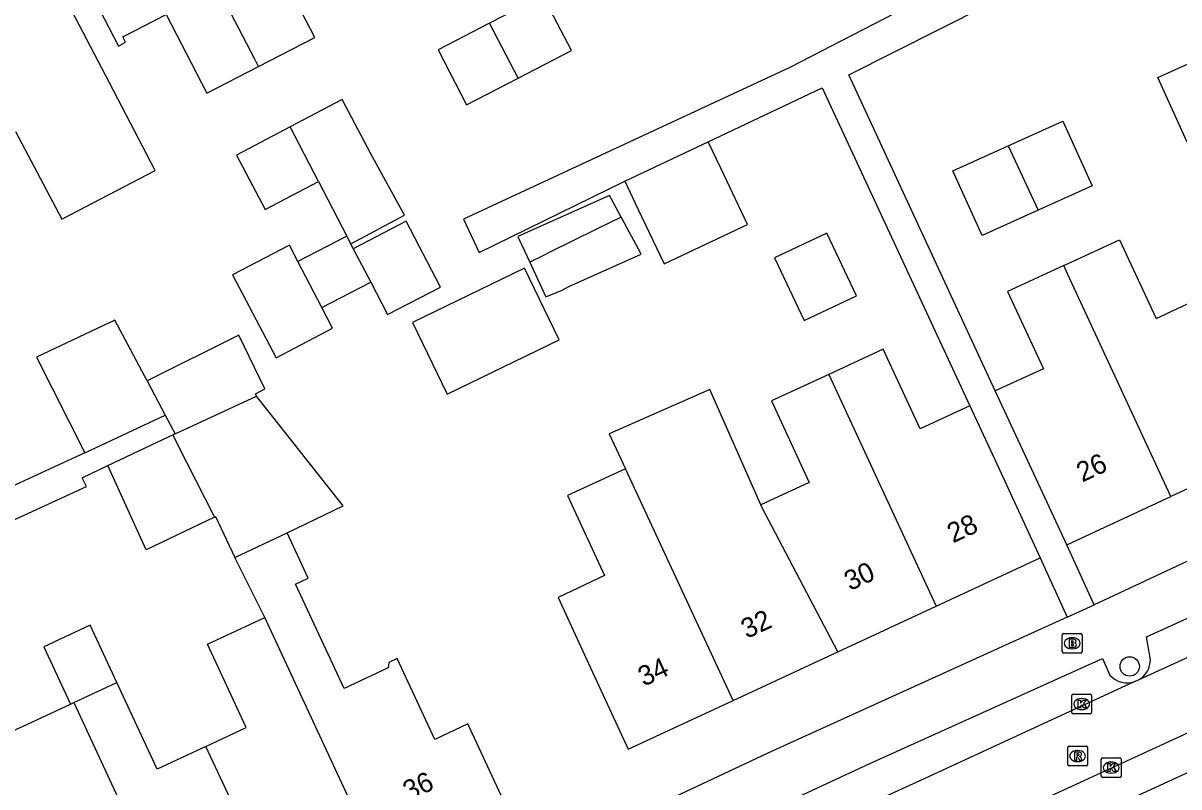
# Model space of a CAD drawing. Extents: x 159265 to 160143, y 383413 to 384319.
# Drawn here: x 159391.1 to 159449.6, y 384205.5 to 384244.2 of the extents above; entities that cross this region are included whole.
import ezdxf

# ---------------------------------------------------------------- set-up
doc = ezdxf.new("R2010")
doc.units = 0
for name, color, linetype in [('IMGEO_Boom', 7, 'Continuous'), ('IMGEO_Brandkraan', 7, 'Continuous'), ('IMGEO_Kolk', 7, 'Continuous'), ('IMGEO_Pand', 7, 'Continuous'), ('IMGEO_Pand_nummerreeks', 7, 'Continuous'), ('IMGEO_Rijbaan_lokaal_open', 7, 'Continuous'), ('IMGEO_Rioolput', 7, 'Continuous'), ('IMGEO_Voetpad_open', 7, 'Continuous')]:
    doc.layers.add(name, color=color, linetype=linetype)

msp = doc.modelspace()

# ---------------------------------------------------------------- linework, layer by layer
at = {"layer": 'IMGEO_Boom'}
msp.add_circle((159447.097, 384211.641), 0.489, dxfattribs=at)
at = {"layer": 'IMGEO_Brandkraan'}
for p, q in [((159443.687, 384212.388), (159443.687, 384213.24)), ((159443.762, 384213.314), (159444.614, 384213.314)), ((159444.688, 384213.24), (159444.688, 384212.388)), ((159444.175, 384213.094), (159444.2, 384213.094)), ((159444.614, 384212.314), (159443.762, 384212.314)), ((159444.198, 384212.534), (159444.173, 384212.534))]:
    msp.add_line(p, q, dxfattribs=at)
for points in [[(159443.687, 384212.388), (159443.687, 384213.24)], [(159443.762, 384213.314), (159444.614, 384213.314)], [(159444.688, 384213.24), (159444.688, 384212.388)], [(159444.035, 384213.014), (159444.035, 384212.614), (159444.248, 384212.614)], [(159444.266, 384213.014), (159444.035, 384213.014)], [(159444.214, 384212.933), (159444.16, 384212.933), (159444.16, 384212.857)], [(159444.16, 384212.857), (159444.213, 384212.857)], [(159444.222, 384212.781), (159444.16, 384212.781), (159444.16, 384212.7)], [(159444.16, 384212.7), (159444.222, 384212.7)], [(159444.614, 384212.314), (159443.762, 384212.314)]]:
    msp.add_lwpolyline(points, dxfattribs=at)
for centre, radius, start, end in [((159443.764, 384213.238), 0.0765, 91.55205, 178.44795), ((159443.764, 384213.238), 0.0765, 91.55205, 178.44795), ((159444.612, 384213.238), 0.0765, 1.55205, 88.44795), ((159444.612, 384213.238), 0.0765, 1.55205, 88.44795), ((159444.215, 384212.895), 0.0379, 267.82845, 90.93552), ((159444.223, 384212.74), 0.0404, 269.87594, 90.50774), ((159444.27, 384212.869), 0.145, 59.4692, 91.53667), ((159444.295, 384212.916), 0.0922, 285.51372, 58.15012), ((159444.3, 384212.724), 0.105, 301.31148, 78.98903), ((159443.764, 384212.39), 0.0765, 181.55205, 268.44795), ((159443.764, 384212.39), 0.0765, 181.55205, 268.44795), ((159444.254, 384212.865), 0.251, 268.66757, 293.53466), ((159444.612, 384212.39), 0.0765, 271.55205, 358.44795), ((159444.612, 384212.39), 0.0765, 271.55205, 358.44795)]:
    msp.add_arc(centre, radius, start, end, dxfattribs=at)
for centre, major_axis, ratio, start_param, end_param in [((159444.174, 384212.814), (-0.387, 0.002), 0.722429, 4.712389, 7.853982), ((159444.199, 384212.814), (-0.39, 0.002), 0.717154, 1.570796, 4.712389)]:
    msp.add_ellipse(centre, major_axis=major_axis, ratio=ratio, start_param=start_param, end_param=end_param, dxfattribs=at)
at = {"layer": 'IMGEO_Kolk'}
for p, q in [((159444.17, 384209.316), (159444.17, 384210.168)), ((159444.245, 384210.242), (159445.097, 384210.242)), ((159444.658, 384210.022), (159444.683, 384210.022)), ((159445.171, 384210.168), (159445.171, 384209.316)), ((159445.097, 384209.242), (159444.245, 384209.242)), ((159444.681, 384209.462), (159444.656, 384209.462)), ((159445.663, 384206.099), (159445.663, 384206.951)), ((159445.738, 384207.025), (159446.59, 384207.025)), ((159446.151, 384206.805), (159446.176, 384206.805)), ((159446.664, 384206.951), (159446.664, 384206.099)), ((159446.174, 384206.245), (159446.149, 384206.245)), ((159446.59, 384206.025), (159445.738, 384206.025))]:
    msp.add_line(p, q, dxfattribs=at)
for points in [[(159444.17, 384209.316), (159444.17, 384210.168)], [(159444.245, 384210.242), (159445.097, 384210.242)], [(159444.491, 384209.942), (159444.614, 384209.942), (159444.614, 384209.791), (159444.744, 384209.942), (159444.908, 384209.942), (159444.762, 384209.791), (159444.915, 384209.542), (159444.763, 384209.542), (159444.678, 384209.706), (159444.614, 384209.639), (159444.614, 384209.542), (159444.491, 384209.542), (159444.491, 384209.942)], [(159445.171, 384210.168), (159445.171, 384209.316)], [(159445.097, 384209.242), (159444.245, 384209.242)], [(159445.663, 384206.099), (159445.663, 384206.951)], [(159445.738, 384207.025), (159446.59, 384207.025)], [(159446.664, 384206.951), (159446.664, 384206.099)], [(159445.984, 384206.725), (159446.107, 384206.725), (159446.107, 384206.574), (159446.237, 384206.725), (159446.401, 384206.725), (159446.255, 384206.574), (159446.408, 384206.325), (159446.256, 384206.325), (159446.171, 384206.489), (159446.107, 384206.422), (159446.107, 384206.325), (159445.984, 384206.325), (159445.984, 384206.725)], [(159446.59, 384206.025), (159445.738, 384206.025)]]:
    msp.add_lwpolyline(points, dxfattribs=at)
for centre, start, end in [((159444.247, 384210.166), 91.55205, 178.44795), ((159444.247, 384210.166), 91.55205, 178.44795), ((159445.095, 384210.166), 1.55205, 88.44795), ((159445.095, 384210.166), 1.55205, 88.44795), ((159444.247, 384209.318), 181.55205, 268.44795), ((159444.247, 384209.318), 181.55205, 268.44795), ((159445.095, 384209.318), 271.55205, 358.44795), ((159445.095, 384209.318), 271.55205, 358.44795), ((159445.74, 384206.949), 91.55205, 178.44795), ((159445.74, 384206.949), 91.55205, 178.44795), ((159446.588, 384206.949), 1.55205, 88.44795), ((159446.588, 384206.949), 1.55205, 88.44795), ((159445.74, 384206.101), 181.55205, 268.44795), ((159445.74, 384206.101), 181.55205, 268.44795), ((159446.588, 384206.101), 271.55205, 358.44795), ((159446.588, 384206.101), 271.55205, 358.44795)]:
    msp.add_arc(centre, 0.0765, start, end, dxfattribs=at)
for centre, major_axis, ratio, start_param, end_param in [((159444.657, 384209.742), (-0.387, 0.002), 0.722429, 4.712389, 7.853982), ((159444.682, 384209.742), (-0.39, 0.002), 0.717154, 1.570796, 4.712389), ((159446.15, 384206.525), (-0.387, 0.002), 0.722429, 4.712389, 7.853982), ((159446.175, 384206.525), (-0.39, 0.002), 0.717154, 1.570796, 4.712389)]:
    msp.add_ellipse(centre, major_axis=major_axis, ratio=ratio, start_param=start_param, end_param=end_param, dxfattribs=at)
at = {"layer": 'IMGEO_Pand'}
for points in [[(159403.053, 384241.99), (159402.858, 384242.366), (159398.89, 384250), (159397.074, 384253.494)], [(159391.947, 384250.825), (159392.372, 384250), (159395.969, 384243.009), (159396.322, 384243.219), (159396.182, 384243.491), (159398.382, 384244.625), (159400.435, 384240.641), (159403.053, 384241.99)], [(159390.768, 384238.692), (159393.102, 384234.267), (159397.827, 384236.735), (159395.511, 384241.169), (159393.22, 384245.555), (159390.963, 384250), (159390.833, 384250.255)], [(159403.053, 384241.99), (159405.892, 384243.452), (159403.876, 384247.366), (159406.076, 384248.5)], [(159416.175, 384241.394), (159418.869, 384242.793), (159417.423, 384245.577), (159414.729, 384244.178)], [(159414.729, 384244.178), (159412.126, 384242.826), (159413.572, 384240.042), (159416.175, 384241.394)], [(159416.175, 384241.394), (159414.729, 384244.178)], [(159452.828, 384239.442), (159449.999, 384238.16), (159448.517, 384241.429), (159451.317, 384242.698)], [(159407.714, 384233.022), (159410.425, 384234.463), (159408.73, 384237.571), (159407.282, 384240.32), (159404.644, 384238.93)], [(159440.96, 384237.972), (159443.712, 384239.219), (159445.194, 384235.95), (159442.471, 384234.716)], [(159404.644, 384238.93), (159401.941, 384237.507), (159403.39, 384234.757), (159406.077, 384236.173)], [(159406.077, 384236.173), (159404.644, 384238.93)], [(159421.573, 384236.183), (159425.789, 384238.182)], [(159421.573, 384236.183), (159422.234, 384234.788), (159423.555, 384232.003), (159427.771, 384234.003), (159426.419, 384236.853), (159425.789, 384238.182)], [(159442.471, 384234.716), (159439.642, 384233.434), (159438.16, 384236.703), (159440.96, 384237.972)], [(159440.96, 384237.972), (159442.471, 384234.716)], [(159406.077, 384236.173), (159407.512, 384233.411)], [(159421.385, 384234.368), (159420.881, 384235.305), (159420.793, 384235.468), (159416.159, 384233.382), (159416.277, 384233.127), (159416.359, 384232.951), (159416.76, 384232.086)], [(159421.385, 384234.368), (159420.144, 384233.756), (159417.782, 384232.59), (159417.462, 384232.432), (159416.76, 384232.086)], [(159416.76, 384232.086), (159416.829, 384231.938), (159417.573, 384230.335), (159418.406, 384230.681), (159418.734, 384230.858), (159422.39, 384232.503), (159422.255, 384232.753), (159421.549, 384234.063), (159421.385, 384234.368)], [(159408.725, 384231.078), (159409.578, 384229.439), (159412.25, 384230.829), (159410.517, 384234.161), (159407.844, 384232.771)], [(159407.512, 384233.411), (159405.041, 384232.126)], [(159407.714, 384233.022), (159407.512, 384233.411)], [(159429.143, 384232.309), (159430.647, 384229.139), (159433.284, 384230.391), (159431.781, 384233.56), (159429.143, 384232.309)], [(159443.768, 384231.919), (159446.586, 384233.226), (159448.432, 384229.247), (159450.777, 384230.335)], [(159405.041, 384232.126), (159404.612, 384232.951), (159401.743, 384231.452), (159403.937, 384227.251), (159406.799, 384228.746), (159406.254, 384229.794)], [(159407.844, 384232.771), (159407.714, 384233.022)], [(159407.844, 384232.771), (159408.725, 384231.078)], [(159406.254, 384229.794), (159405.041, 384232.126)], [(159416.492, 384231.786), (159410.828, 384229.031), (159412.589, 384225.41), (159418.253, 384228.165), (159416.492, 384231.786)], [(159443.768, 384231.919), (159440.927, 384230.601), (159442.735, 384226.703), (159440.303, 384225.576)], [(159449.182, 384220.245), (159443.977, 384231.468), (159443.768, 384231.919)], [(159406.254, 384229.794), (159408.725, 384231.078)], [(159397.415, 384226.089), (159395.793, 384229.163), (159391.817, 384227.294), (159394.262, 384222.444)], [(159402.946, 384225.317), (159402.895, 384225.426), (159403.367, 384225.677), (159402.049, 384228.406), (159397.415, 384226.089)], [(159439.011, 384224.828), (159436.5, 384223.663), (159434.633, 384227.688), (159431.88, 384226.411)], [(159397.415, 384226.089), (159398.329, 384224.355)], [(159431.88, 384226.411), (159428.986, 384225.069), (159430.895, 384220.952), (159428.449, 384219.818)], [(159431.88, 384226.411), (159437.318, 384214.694)], [(159428.449, 384219.818), (159425.875, 384225.653), (159420.786, 384223.409), (159421.604, 384221.646)], [(159443.911, 384217.798), (159441.807, 384222.334), (159440.303, 384225.576)], [(159398.828, 384223.409), (159402.946, 384225.317)], [(159404.494, 384218.407), (159405.923, 384219.09), (159407.327, 384219.761), (159402.946, 384225.317)], [(159394.262, 384222.444), (159398.329, 384224.355)], [(159398.329, 384224.355), (159398.828, 384223.409)], [(159439.011, 384224.828), (159440.476, 384221.67), (159442.579, 384217.134)], [(159395.437, 384221.807), (159398.533, 384223.273), (159398.718, 384223.358)], [(159398.828, 384223.409), (159398.718, 384223.358)], [(159398.718, 384223.358), (159398.945, 384222.907), (159400.82, 384219.192)], [(159454.347, 384222.639), (159449.182, 384220.245)], [(159400.82, 384219.192), (159397.365, 384217.548), (159395.437, 384221.807)], [(159421.604, 384221.646), (159418.673, 384220.286), (159420.55, 384216.239), (159418.208, 384215.123), (159419.633, 384212.002), (159421.737, 384207.466), (159427.041, 384209.926)], [(159427.041, 384209.926), (159421.604, 384221.646)], [(159443.911, 384217.798), (159449.182, 384220.245)], [(159432.339, 384212.384), (159428.498, 384219.706), (159428.449, 384219.818)], [(159400.82, 384219.192), (159400.879, 384219.22), (159401.861, 384217.148)], [(159401.861, 384217.148), (159404.494, 384218.407)], [(159409.262, 384201.415), (159415.659, 384204.382), (159413.635, 384208.745), (159411.957, 384207.952), (159410.062, 384212.037), (159409.638, 384211.84), (159409.613, 384211.566), (159407.375, 384210.528), (159405.297, 384215.008), (159404.926, 384215.808), (159405.563, 384216.103), (159404.494, 384218.407)], [(159403.371, 384214.114), (159401.861, 384217.148)], [(159437.318, 384214.694), (159442.579, 384217.134)], [(159432.339, 384212.384), (159437.318, 384214.694)], [(159400.383, 384207.596), (159402.432, 384208.546), (159400.473, 384212.77), (159403.371, 384214.114)], [(159409.262, 384201.415), (159403.371, 384214.114)], [(159395.893, 384210.824), (159394.546, 384213.727), (159392.202, 384212.639), (159393.549, 384209.736)], [(159427.041, 384209.926), (159432.339, 384212.384)], [(159393.714, 384209.813), (159395.893, 384210.824)], [(159400.383, 384207.596), (159397.92, 384206.453), (159395.893, 384210.824)], [(159388.855, 384207.587), (159391.119, 384208.609), (159393.549, 384209.736)], [(159393.549, 384209.736), (159393.714, 384209.813)], [(159393.714, 384209.813), (159399.666, 384196.963)], [(159404.34, 384199.132), (159400.383, 384207.596)]]:
    msp.add_lwpolyline(points, dxfattribs=at)
at = {"layer": 'IMGEO_Rijbaan_lokaal_open'}
for points in [[(159447.581, 384210.982), (159456.855, 384215.239), (159462.918, 384218.05), (159469.317, 384221.008)], [(159470.723, 384217.848), (159470.602, 384217.793), (159461.9, 384213.745), (159458.611, 384212.225), (159441.592, 384204.385)], [(159447.362, 384210.879), (159447.581, 384210.982)], [(159447.362, 384210.879), (159437.872, 384206.492), (159436.516, 384205.872), (159434.447, 384204.925), (159432.68, 384204.089), (159429.034, 384202.43)]]:
    msp.add_lwpolyline(points, dxfattribs=at)
at = {"layer": 'IMGEO_Rioolput'}
for p, q in [((159443.965, 384206.683), (159443.965, 384207.535)), ((159444.04, 384207.609), (159444.892, 384207.609)), ((159444.453, 384207.389), (159444.478, 384207.389)), ((159444.966, 384207.535), (159444.966, 384206.683)), ((159444.476, 384206.829), (159444.451, 384206.829)), ((159444.892, 384206.609), (159444.04, 384206.609))]:
    msp.add_line(p, q, dxfattribs=at)
for points in [[(159443.965, 384206.683), (159443.965, 384207.535)], [(159444.04, 384207.609), (159444.892, 384207.609)], [(159444.966, 384207.535), (159444.966, 384206.683)], [(159444.554, 384207.307), (159444.302, 384207.309), (159444.302, 384206.909)], [(159444.302, 384206.909), (159444.426, 384206.909), (159444.426, 384207.071), (159444.437, 384207.071)], [(159444.48, 384207.228), (159444.426, 384207.228), (159444.426, 384207.147)], [(159444.426, 384207.147), (159444.478, 384207.147)], [(159444.484, 384207.042), (159444.555, 384206.909), (159444.695, 384206.909), (159444.63, 384207.035)], [(159444.892, 384206.609), (159444.04, 384206.609)]]:
    msp.add_lwpolyline(points, dxfattribs=at)
for centre, radius, start, end in [((159444.042, 384207.533), 0.0765, 91.55205, 178.44795), ((159444.042, 384207.533), 0.0765, 91.55205, 178.44795), ((159444.89, 384207.533), 0.0765, 1.55205, 88.44795), ((159444.89, 384207.533), 0.0765, 1.55205, 88.44795), ((159444.436, 384207.018), 0.0533, 26.02933, 88.69889), ((159444.462, 384207.336), 0.19, 274.7715, 282.96867), ((159444.486, 384207.132), 0.0964, 77.00612, 93.18647), ((159444.5, 384207.189), 0.0378, 276.66336, 79.67722), ((159444.553, 384207.197), 0.109, 350.36119, 89.41601), ((159444.551, 384207.197), 0.112, 277.58423, 350.98172), ((159444.535, 384206.982), 0.108, 29.51342, 73.79051), ((159444.042, 384206.685), 0.0765, 181.55205, 268.44795), ((159444.042, 384206.685), 0.0765, 181.55205, 268.44795), ((159444.89, 384206.685), 0.0765, 271.55205, 358.44795), ((159444.89, 384206.685), 0.0765, 271.55205, 358.44795)]:
    msp.add_arc(centre, radius, start, end, dxfattribs=at)
for centre, major_axis, ratio, start_param, end_param in [((159444.452, 384207.109), (-0.387, 0.002), 0.722429, 4.712389, 7.853982), ((159444.477, 384207.109), (-0.39, 0.002), 0.717154, 1.570796, 4.712389)]:
    msp.add_ellipse(centre, major_axis=major_axis, ratio=ratio, start_param=start_param, end_param=end_param, dxfattribs=at)
at = {"layer": 'IMGEO_Voetpad_open'}
for points in [[(159436.516, 384264.134), (159444.184, 384249.322), (159429.914, 384241.934), (159413.417, 384234.259), (159414.2, 384232.576), (159421.573, 384236.183)], [(159440.303, 384225.576), (159432.891, 384241.57), (159458.422, 384254.443)], [(159425.789, 384238.182), (159431.549, 384240.913), (159439.011, 384224.828)], [(159475.108, 384232.269), (159476.465, 384229.34), (159445.521, 384214.855), (159445.294, 384214.752)], [(159394.262, 384222.444), (159388.767, 384219.921)], [(159448.144, 384211.983), (159447.955, 384213.139), (159456.019, 384216.815), (159462.387, 384219.8), (159467.663, 384222.276), (159468.052, 384221.521)], [(159370.59, 384209.832), (159386.352, 384217.072), (159394.355, 384220.749), (159394.133, 384221.19), (159395.437, 384221.807)], [(159445.294, 384214.752), (159443.911, 384217.798)], [(159442.579, 384217.134), (159443.94, 384214.137)], [(159442.747, 384203.913), (159443.14, 384203.112), (159459.195, 384210.497), (159462.832, 384212.209), (159470.68, 384215.856), (159470.382, 384216.534)], [(159443.94, 384214.137), (159445.294, 384214.752)], [(159443.94, 384214.137), (159429.018, 384207.361), (159405.051, 384196.117), (159368.336, 384179.241), (159356.231, 384172.876), (159341.528, 384164.55), (159333.688, 384159.631)], [(159429.583, 384204.692), (159433.959, 384206.734), (159445.719, 384212.037), (159446.099, 384211.198)]]:
    msp.add_lwpolyline(points, dxfattribs=at)
for centre, radius, start, end in [((159446.974, 384211.982), 1.17, 301.24506, 0.04487), ((159446.966, 384211.973), 1.163, 221.76823, 289.88192)]:
    msp.add_arc(centre, radius, start, end, dxfattribs=at)

# ---------------------------------------------------------------- texts
at = {"layer": 'IMGEO_Pand_nummerreeks'}
for s, rotation, p in [('26', 24.88464, (159444.7, 384220.942)), ('28', 24.88522, (159438.166, 384217.865)), ('30', 24.88522, (159432.956, 384215.448)), ('32', 24.88522, (159427.739, 384213.028)), ('34', 24.88522, (159422.532, 384210.612)), ('36', 24.88356, (159410.65, 384204.837))]:
    msp.add_text(s, height=1, rotation=rotation, dxfattribs=at).set_placement(p)

doc.saveas('drawing.dxf')
